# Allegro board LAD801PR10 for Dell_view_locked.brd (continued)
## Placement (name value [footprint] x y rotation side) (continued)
RC11  80.6_0402_1%  [R_0402]  92.58 39.82 180 top
RC12  100_0402_1%  [R_0402]  92.55 38.94 180 top
RC13  10K_0402_5%  [R_0402]  91.64 31.46 0 top
RC14  10K_0402_5%  [R_0402]  91.64 30.57 0 top
RC15  22_0402_5%  [R_0402]  96.11 25.19 270 bottom
RC16  22_0402_5%  [R_0402]  96.93 28.96 180 bottom
RC17  0_0603_5%  [R0603_0OHM]  88.47 21.74 180 top
RC18  4.7K_0402_5%  [R_0402]  105.94 22.12 90 bottom
RC19  1K_0402_5%  [R_0402]  106.85 20.54 180 bottom
RC20  1K_0402_5%  [R_0402]  92.96 15.54 0 bottom
RC21  33_0402_5%  [R_0402]  105.67 13.17 0 bottom
RC22  33_0402_5%  [R_0402]  103.78 25.18 270 bottom
RC23  33_0402_5%  [R_0402]  101.67 25.19 270 bottom
RC24  33_0402_5%  [R_0402]  99.89 25.19 270 bottom
RC25  33_0402_5%  [R_0402]  99 25.19 270 bottom
RC26  33_0402_5%  [R_0402]  102.76 25.18 270 bottom
RC27  2.2K_0402_5%  [R_0402]  113.48 25.86 0 top
RC28  2.2K_0402_5%  [R_0402]  114.65 21.68 180 top
RC29  1K_0402_5%  [R_0402]  114.57 22.83 270 bottom
RC30  1K_0402_5%  [R_0402]  115.46 22.83 270 bottom
RC31  1K_0402_5%  [R_0402]  115.53 25.12 270 bottom
RC32  1K_0402_5%  [R_0402]  116.41 25.12 270 bottom
RC33  1K_0402_5%  [R_0402]  118.01 25.18 270 bottom
RC34  1K_0402_5%  [R_0402]  113.75 25.12 270 bottom
RC35  8.2K_0402_5%  [R_0402]  98.22 33.7 225 bottom
RC36  8.2K_0402_5%  [R_0402]  97.06 31.13 180 bottom
RC37  8.2K_0402_5%  [R_0402]  113.68 22.83 270 bottom
RC38  10K_0402_5%  [R_0402]  114.64 25.12 270 bottom
RC39  150K_0402_5%  [R_0402]  110.57 21.73 90 bottom
RC40  1K_0402_1%  [R_0402]  100.78 24.28 90 bottom
RC41  1K_0402_1%  [R_0402]  106.85 19.65 180 bottom
RC42  10K_0402_5%  [R_0402]  111.91 21.91 90 bottom
RC43  49.9K_0402_1%  [R_0402]  111.7 26.37 0 top
RC44  4.7K_0402_5%  [R_0402]  97.35 24.3 90 bottom
RC45  10K_0402_5%  [R_0402]  88.23 22.82 180 top
RC46  10K_0402_5%  [R_0402]  119.81 25.19 270 bottom
RC47  10K_0402_5%  [R_0402]  109.94 25.06 270 bottom
RC48  10K_0402_5%  [R_0402]  118.9 25.18 270 bottom
RC49  10K_0402_5%  [R_0402]  116.99 21.86 90 bottom
RC50  150K_0402_5%  [R_0402]  117.87 21.86 90 bottom
RC51  10K_0402_5%  [R_0402]  96.41 27.93 0 bottom
RC52  10K_0402_5%  [R_0402]  97.33 27.04 180 bottom
RC53  10K_0402_5%  [R_0402]  85.62 27.25 90 top
RC54  10K_0402_5%  [R_0402]  86.51 28.17 270 top
RC55  10K_0402_5%  [R_0402]  112.79 21.92 90 bottom
RC56  10K_0402_5%  [R_0402]  112.86 25.12 270 bottom
RC57  10K_0402_5%  [R_0402]  85.55 25.56 270 top
RC58  10K_0402_5%  [R_0402]  86.44 24.65 90 top
RC59  10K_0402_5%  [R_0402]  84.73 27.25 90 top
RC60  10K_0402_5%  [R_0402]  90.46 30.69 180 top
RC61  10K_0402_5%  [R_0402]  87.46 27.21 270 top
RC62  10K_0402_5%  [R_0402]  88.35 26.3 90 top
RC63  10K_0402_5%  [R_0402]  117.11 20.39 0 bottom
RC64  10K_0402_5%  [R_0402]  120.85 24.28 90 bottom
RC65  100_0402_1%  [R_0402]  119.45 30.82 0 top
RC66  113_0402_1%  [R_0402]  112.26 32.14 90 top
RC67  1K_0402_5%  [R_0402]  109.05 25.06 270 bottom
RC68  1K_0402_5%  [R_0402]  108.16 25.06 270 bottom
RC69  10K_0402_5%  [R_0402]  121.89 25.19 270 bottom
RC70  10K_0402_5%  [R_0402]  120.31 27.83 270 top
RC71  10K_0402_5%  [R_0402]  87.38 24.85 0 top
RC72  10K_0402_5%  [R_0402]  96.44 26.15 0 bottom
RC73  10K_0402_5%  [R_0402]  87.38 23.96 0 top
RC74  0_0402_5%  [R_0402]  83.08 22.81 90 top
RC75  0_0402_5%  [R_0402]  82.12 21.22 90 top
RC76  2.71K_0402_1%  [R_0402]  125.74 50.88 0 bottom
RC77  20K_0402_5%  [R_0402]  91.65 21.5 270 top
RC78  20K_0402_5%  [R_0402]  89.86 20.6 0 top
RC80  1M_0402_1%  [R_0402]  129.33 47.78 90 bottom
RC82  10M_0402_5%  [R_0402]  91.38 28.22 0 top
RC83  0_0402_5%  [R0402_0OHM]  89.6 28.22 0 top
RC84  10K_0402_5%  [R_0402]  92.55 22.63 180 top
RC85  10K_0402_5%  [R_0402]  93.52 13.1 0 bottom
RC86  10K_0402_5%  [R_0402]  122.78 24.28 90 bottom
RC87  100K_0402_5%  [R_0402]  97.19 38.5 180 bottom
RC88  10K_0402_5%  [R_0402]  36.4 3.12 90 top
RC89  8.2K_0402_5%  [R_0402]  89.03 33.04 0 top
RC90  10K_0402_5%  [R_0402]  92.36 34.19 180 top
RC91  330K_0402_5%  [R_0402]  85.93 23.33 180 top
RC92  10K_0402_5%  [R_0402]  108.03 18.9 270 bottom
RC93  100K_0402_5%  [R_0402]  89.95 34 180 top
RC94  10K_0402_5%  [R_0402]  83.11 24.97 90 top
RC95  1K_0402_5%  [R_0402]  125.82 73.24 180 bottom
RC96  60.4_0402_1%  [R_0402]  127.67 68.29 180 bottom
RC97  0_0402_5%  [R0402_0OHM]  98.63 38.49 90 bottom
RC99  0_0402_5%  [R0402_0OHM]  83.97 20.2 90 top
RC100  0_0402_5%  [R_0402]  95.3 12.21 90 bottom
RC102  1M_0402_5%  [R_0402]  84.92 14.77 270 top
RC103  10K_0402_1%  [R_0402]  88.86 10.93 90 top
RC104  1K_0402_5%  [R_0402]  130.63 54.45 180 bottom
RC105  10K_0402_5%  [R_0402]  125.85 24.28 0 bottom
RC106  0_0402_5%  [R0402_0OHM]  128.52 24.28 180 bottom
RC107  0_0402_5%  [R0402_0OHM]  126.77 25.16 180 bottom
RC108  0_0402_5%  [R_0402]  105.95 14.1 90 bottom
RC109  100K_0402_5%  [R_0402]  105.95 15.87 90 bottom
RC110  1K_0402_5%  [R_0402]  83.97 23.72 270 top
RC111  49.9_0402_1%  [R_0402]  127.48 63.05 180 bottom
RC112  1K_0402_5%  [R_0402]  128.34 63.02 0 bottom
RC113  1K_0402_5%  [R_0402]  129.45 67.71 180 bottom
RC114  10K_0402_5%  [R_0402]  93.17 17.29 180 bottom
RC115  10K_0402_5%  [R_0402]  130.26 28.78 90 bottom
RC116  10K_0402_5%  [R_0402]  129.32 29.81 180 bottom
RC117  499_0402_1%  [R_0402]  127.6 67.33 180 bottom
RC118  0_0402_5%  [R_0402]  129.32 30.69 180 bottom
RC119  49.9_0402_1%  [R_0402]  92.55 36.28 180 top
RC120  49.9_0402_1%  [R_0402]  92.55 37.17 180 top
RC121  49.9_0402_1%  [R_0402]  126.75 70.06 0 bottom
RC122  49.9_0402_1%  [R_0402]  126.75 69.18 0 bottom
RC123  33_0402_5%  [R_0402]  78.52 21.12 90 top
RC124  33_0402_5%  [R_0402]  80.79 18.05 90 top
RC125  33_0402_5%  [R_0402]  79.9 18.05 90 top
RC126  1K_0402_5%  [R_0402]  79.01 18.05 90 top
RC127  33_0402_5%  [R_0402]  79.42 21.11 90 top
RC128  8.2K_0402_5%  [R_0402]  108.96 18.64 90 bottom
RC129  4.7K_0402_5%  [R_0402]  109.85 18.64 90 bottom
RC130  200_0402_1%  [R_0402]  110.89 25.06 270 bottom
RC131  10K_0402_1%  [R_0402]  128.56 73.19 270 bottom
RC132  10K_0402_1%  [R_0402]  127.64 73.2 180 bottom
RC133  10K_0402_1%  [R_0402]  123.84 73.25 270 bottom
RC134  49.9_0402_1%  [R_0402]  128.34 62.06 0 bottom
RC136  10K_0402_1%  [R_0402]  120.35 69.92 90 top
RC137  0_0402_5%  [R_0402]  113.3 29.22 90 top
RC138  100K_0402_5%  [R_0402]  128.48 66.84 270 bottom
RC139  1K_0402_5%  [R_0402]  92.96 14.65 0 bottom
RC140  51_0402_5%  [R_0402]  128.34 61.11 0 bottom
RC141  51_0402_5%  [R_0402]  119.08 61.99 90 top
RC142  51_0402_5%  [R_0402]  128.15 58.82 0 bottom
RC143  1K_0402_5%  [R_0402]  131.77 22.45 180 bottom
RC144  0_0402_5%  [R_0402]  130.33 73.23 180 bottom
RC145  0_0402_5%  [R_0402]  105.91 18.1 0 bottom
RC146  51_0402_1%  [R_0402]  126.56 62.16 0 bottom
RC147  51_0402_5%  [R_0402]  129.04 59.71 0 bottom
RC148  1K_0402_5%  [R_0402]  82.19 25.88 270 top
RC149  0_0603_5%  [R_0603]  132.81 23.63 270 bottom
RC150  100_0402_1%  [R_0402]  132.04 52.14 90 top
RC151  100_0402_1%  [R_0402]  132.04 53.92 90 top
RC152  56_0402_1%  [R_0402]  129.38 64.79 180 bottom
RC153  220_0402_5%  [R_0402]  126.69 64.79 0 bottom
RC154  100_0402_1%  [R_0402]  127.6 66.38 180 bottom
RC155  100_0402_1%  [R_0402]  117.37 72.36 270 bottom
RC156  100_0402_1%  [R_0402]  116.41 71.45 90 bottom
RC157  100_0402_1%  [R_0402]  107.71 61.67 90 top
RC158  100_0402_1%  [R_0402]  106.89 63.45 90 top
RC159  100_0402_1%  [R_0402]  117.52 41.57 315 top
RC160  100_0402_1%  [R_0402]  119 41.53 90 top
RC161  0_0603_5%  [R0603_0OHM]  130.44 45.1 0 bottom
RC162  0_0603_5%  [R0603_0OHM]  131.4 43.83 0 bottom
RC163  0_0603_5%  [R0603_0OHM]  92.74 15.25 180 top
RC164  10K_0402_5%  [R_0402]  85.93 15.71 90 top
RC169  0_0603_5%  [R0603_0OHM]  131.45 28.13 270 bottom
RC170  0_0603_5%  [R0603_0OHM]  135.38 41.6 180 top
RC171  0_0603_5%  [R0603_0OHM]  135.26 44.08 270 top
RC173  0_0603_5%  [R0603_0OHM]  135.47 45.23 270 bottom
RC174  0_0603_5%  [R0603_0OHM]  130.3 23.52 0 bottom
RC175  0_0402_5%  [R_0402]  130.77 75.09 270 bottom
RC176  15_0402_1%  [R_0402]  116.27 18.06 0 bottom
RC177  15_0402_1%  [R_0402]  113.51 17.8 180 bottom
RC178  15_0402_1%  [R_0402]  108.68 12.1 180 bottom
RC179  15_0402_1%  [R_0402]  108.68 11.21 180 bottom
RC180  15_0402_1%  [R_0402]  119.44 12.57 0 bottom
RC181  10K_0402_5%  [R_0402]  117.11 19.5 0 bottom
RC182  10K_0402_5%  [R_0402]  115.74 19.45 180 bottom
RC187  10K_0402_5%  [R_0402]  97.77 32 45 bottom
RC188  10K_0402_5%  [R_0402]  76.52 17.04 0 top
RC189  0_0402_5%  [R_0402]  81.24 21.09 90 top
RC190  10K_0402_5%  [R_0402]  85.88 20.31 0 top
RC191  10K_0402_5%  [R_0402]  86.81 19.41 180 top
RC192  1M_0402_1%  [R_0402]  87.99 10.95 180 top
RD1  0_0402_5%  [R_0402]  60.28 18.93 90 top
RD2  0_0402_5%  [R_0402]  66.39 19.77 180 top
RD3  0_0402_5%  [R_0402]  58.57 41.16 90 top
RD4  0_0402_5%  [R0402_0OHM]  61.17 19.85 270 top
RD5  0_0402_5%  [R0402_0OHM]  64.6 19.79 270 top
RD6  0_0402_5%  [R0402_0OHM]  59.45 42.07 270 top
RD7  470_0402_1%  [R_0402]  58.44 63.54 0 top
RD8  0_0402_5%  [R0402_0OHM]  60.21 62.63 90 top
RD9  2_0402_1%  [R_0402]  57.73 43.39 0 top
RD10  1K_0402_1%~D  [R_0402]  58.63 46.07 270 top
RD11  24.9_0402_1%  [R_0402]  55.95 44.28 0 top
RD12  1K_0402_1%~D  [R_0402]  58.64 44.28 180 top
RD13  0_0402_5%  [R_0402]  50.95 20.61 270 top
RD14  0_0402_5%  [R0402_0OHM]  45.73 20.66 0 top
RD15  0_0402_5%  [R_0402]  44.46 43.33 0 top
RD16  0_0402_5%  [R0402_0OHM]  50.06 20.61 270 top
RD17  0_0402_5%  [R_0402]  47.47 21.68 180 top
RD18  0_0402_5%  [R0402_0OHM]  45.37 42.44 180 top
RD19  2_0402_1%  [R_0402]  44.46 46.06 0 top
RD20  1K_0402_1%~D  [R_0402]  44.46 46.95 0 top
RD21  1K_0402_1%~D  [R_0402]  45.37 45.17 180 top
RD22  24.9_0402_1%  [R_0402]  42.68 45.17 0 top
RD23  240_0402_1%  [R_0402]  58.68 53.87 0 top
RD24  240_0402_1%  [R_0402]  44.85 53.73 90 top
RE1  100K_0402_1%  [R_0402]  148.34 13.31 0 bottom
RE2  0_0603_5%  [R0603_0OHM]  141.18 19.26 180 top
RE3  100K_0402_1%  [R_0402]  151.03 21.41 180 top
RE4  100K_0402_1%  [R_0402]  151.03 20.52 180 top
RE6  100K_0402_1%  [R_0402]  147.83 14.18 0 bottom
RE7  0_0603_5%  [R0603_0OHM]  146.26 13.99 270 bottom
RE8  4.7K_0402_5%  [R_0402]  138.46 20.6 180 bottom
RE9  4.7K_0402_5%  [R_0402]  138.46 21.49 180 bottom
RE10  2.2K_0402_5%  [R_0402]  138.46 22.5 180 bottom
RE11  2.2K_0402_5%  [R_0402]  138.46 23.39 180 bottom
RE12  10K_0402_5%  [R_0402]  139.73 34.57 180 bottom
RE13  10K_0402_5%  [R_0402]  144.91 32.85 0 top
RE14  100K_0402_5%  [R_0402]  141.51 34.57 180 bottom
RE15  100K_0402_5%  [R_0402]  155.26 29.87 0 top
RE16  10K_0402_5%  [R_0402]  153.56 28.26 90 top
RE17  100K_0402_5%  [R_0402]  138.4 24.85 180 bottom
RE18  100K_0402_5%  [R_0402]  138.46 18.69 180 bottom
RE19  1K_0402_5%  [R_0402]  153.64 25.04 180 top
RE20  10K_0402_5%  [R_0402]  157.87 22.12 0 bottom
RE21  100K_0402_5%  [R_0402]  154.32 14.9 270 top
RE22  0_0402_5%  [R0402_0OHM]  155.58 20.47 0 top
RE23  43_0402_1%  [R_0402]  158.13 18.39 270 top
RE24  0_0402_5%  [R_0402]  147.83 14.18 0 top
RE25  100K_0402_5%  [R_0402]  144.98 35.96 0 top
RE26  0_0402_5%  [R_0402]  154.66 16.27 180 top
RE27  0_0402_5%  [R_0402]  153.26 33.36 180 top
RE28  0_0402_5%  [R0402_0OHM]  146.27 15.22 180 top
RE29  1K_0402_5%  [R_0402]  146.27 19.58 90 top
RE30  100K_0402_5%  [R_0402]  142.63 17.49 0 top
RE32  100K_0402_5%  [R_0402]  145.38 19.58 90 top
RE33  15_0402_1%  [R_0402]  138.07 30.8 90 bottom
RE34  15_0402_1%  [R_0402]  137.55 28.26 0 bottom
RE35  15_0402_1%  [R_0402]  137.55 29.14 0 bottom
RE37  0_0402_5%  [R0402_0OHM]  137.94 27.21 270 bottom
RE38  0_0402_5%  [R0402_0OHM]  136.94 26.82 180 bottom
RE40  10K_0402_5%  [R_0402]  145.62 17.69 270 top
RE41  100K_0402_5%  [R_0402]  139.46 14.11 90 bottom
RE42  0_0402_5%  [R0402_0OHM]  147.94 34.61 180 bottom
RE43  100_0402_5%  [R_0402]  140.35 15.02 270 bottom
RE44  0_0402_5%  [R_0402]  148.75 15.07 180 top
RE45  0_0402_5%  [R_0402]  142.93 13.54 180 bottom
RE46  10K_0402_1%  [R_0402]  143.22 28.54 180 top
RE47  0_0402_5%  [R_0402]  143.77 14.57 0 bottom
RE48  10K_0402_1%  [R_0402]  140.93 28.79 270 top
RE49  100K_0402_5%  [R_0402]  144.3 26.69 180 top
RE50  0_0603_5%  [R0603_0OHM]  148.58 17 0 top
RE51  300_0402_5%  [R_0402]  149.22 19.57 90 top
RE52  100K_0402_5%  [R_0402]  143.01 25.8 0 top
RE53  100K_0402_5%  [R_0402]  152.84 23.95 0 top
RE54  300_0402_5%  [R_0402]  147.43 19.57 90 top
RE55  10K_0402_5%  [R_0402]  132.73 11.09 270 top
RE56  10K_0402_5%  [R_0402]  136.29 12.41 270 top
RE57  100K_0402_5%  [R_0402]  133.62 11.09 270 top
RE58  49.9_0402_1%  [R_0402]  128.29 11.09 270 top
RE59  10K_0402_5%  [R_0402]  133.61 12.78 0 top
RE60  0_0402_5%  [R0402_0OHM]  134.53 14.69 180 top
RE61  0_0402_5%  [R0402_0OHM]  136.3 14.05 180 top
RE63  0_0402_5%  [R0402_0OHM]  134.53 13.67 180 top
RE64  0_0402_5%  [R0402_0OHM]  149.44 15.96 180 top
RI1  5.6_0402_1%  [R_0402]  17.29 86.32 180 top
RI2  5.6_0402_1%  [R_0402]  17.29 87.21 180 top
RI3  150_0402_5%  [R_0402]  14.93 87.22 270 top
RI4  5.6_0402_1%  [R_0402]  17.29 89.75 180 top
RI5  5.6_0402_1%  [R_0402]  17.29 88.86 180 top
RI6  150_0402_5%  [R_0402]  14.93 89.83 270 top
RI7  5.6_0402_1%  [R_0402]  17.29 81.24 180 top
RI8  5.6_0402_1%  [R_0402]  17.29 82.13 180 top
RI9  150_0402_5%  [R_0402]  14.93 82.14 270 top
RI10  5.6_0402_1%  [R_0402]  17.29 83.78 180 top
RI11  5.6_0402_1%  [R_0402]  17.29 84.67 180 top
RI12  150_0402_5%  [R_0402]  14.93 84.68 270 top
RI13  2.2K_0402_5%  [R_0402]  26.7 95.46 180 top
RI14  2.2K_0402_5%  [R_0402]  26.7 96.48 180 top
RI15  1M_0402_5%  [R_0402]  24.85 93.06 270 top
RI16  20K_0402_5%  [R_0402]  29.29 92.17 270 top
RL1  10K_0402_5%  [R_0402]  35.38 123.15 0 bottom
RL2  2.49K_0402_1%~D  [R_0402]  39.27 115.72 180 bottom
RL3  1K_0402_5%  [R_0402]  34.94 121.7 270 bottom
RL4  15K_0402_1%  [R_0402]  35.96 120.79 90 bottom
RL5  0_0603_5%  [R0603_0OHM]  38.56 115.4 90 top
RL6  100K_0402_5%  [R_0402]  25.55 122.57 90 bottom
RL7  10K_0402_5%  [R_0402]  25.55 121.7 270 bottom
RL12  0_0402_5%  [R0402_0OHM]  41.12 109.12 180 top
RL13  0_0402_5%  [R0402_0OHM]  27.2 118.69 90 top
RL14  75_0603_5%  [R_0603]  19.89 112.1 180 top
RL15  75_0603_5%  [R_0603]  19.89 108.29 180 top
RL16  10K_0402_5%  [R_0402]  31.2 115.13 90 bottom
RP1  100K_8P4R_5%  [RP_0804_8P4R]  222.9 38.87 0 top
RP2  100_8P4R_5%  [RP_0804_8P4R]  224.11 43.53 180 top
RP34  10K_8P4R_5%  [RP_0804_8P4R]  117.48 95.97 90 bottom
RPC1  10K_8P4R_5%  [RP_0804_8P4R]  130.76 30.96 0 bottom
RPE1  10K_8P4R_5%  [RP_0804_8P4R]  142.92 21.68 0 top
RPE2  10K_8P4R_5%  [RP_0804_8P4R]  152.34 14.06 270 top
RPE3  100K_8P4R_5%  [RP_0804_8P4R]  144.1 23.2 180 top
RPE4  100K_8P4R_5%  [RP_0804_8P4R]  143.35 36.16 270 bottom
RPE5  100K_8P4R_5%  [RP_0804_8P4R]  159.85 29.22 180 bottom
RPE6  100K_8P4R_5%  [RP_0804_8P4R]  159.92 20.84 180 bottom
RPI1  470_8P4R_5%  [RP_0804_8P4R]  15.08 82.29 0 bottom
RPI2  470_8P4R_5%  [RP_0804_8P4R]  15.07 87.11 0 bottom
RS1  0_0402_5%  [R_0402]  195.97 17.28 180 top
RU1  0_0402_5%  [R_0402-NPM]  25.34 57.87 0 top
RU2  0_0402_5%  [R_0402-NPM]  25.34 56.98 0 top
RU3  0_0402_5%  [R_0402]  22.61 61.62 0 top
RU4  0_0402_5%  [R_0402]  22.61 62.51 0 top
RU5  0_0402_5%  [R_0402]  22.61 59.84 0 top
RU6  0_0402_5%  [R_0402]  22.61 60.73 0 top
RU7  0_0402_5%  [R_0402-NPM]  26.76 35.2 180 top
RU8  0_0402_5%  [R_0402-NPM]  26.76 36.09 180 top
RU9  0_0402_5%  [R_0402]  22.8 40.54 0 top
RU10  0_0402_5%  [R_0402]  22.8 41.43 0 top
RU11  0_0402_5%  [R_0402]  22.93 38.19 0 top
RU12  0_0402_5%  [R_0402]  22.93 39.08 0 top
RU13  0_0402_5%  [R_0402-NPM]  173.71 20.43 0 bottom
RU14  0_0402_5%  [R_0402-NPM]  173.71 19.55 0 bottom
RU15  0_0402_5%  [R_0402-NPM]  179.72 20.42 0 bottom
RU16  0_0402_5%  [R_0402-NPM]  179.72 19.53 0 bottom
RV1  1.69K_0402_1%  [R_0402]  110.37 120.04 90 top
RV2  1K_0402_1%  [R_0402]  113.69 109.36 0 top
RV3  1K_0402_1%  [R_0402]  109.29 120.04 90 top
RV4  100K_0402_5%  [R_0402]  98.81 122.38 270 bottom
RV5  45.3K_0402_1%  [R_0402]  111.78 100.6 90 top
RV6  45.3K_0402_1%  [R_0402]  113.16 104.6 0 top
RV8  8.45K_0402_1%  [R_0402]  104.8 115.19 90 top
RV9  2K_0402_1%  [R_0402]  105.7 116.09 270 top
RV11  8.45K_0402_1%  [R_0402]  103 117.53 270 top
RV12  2K_0402_1%  [R_0402]  103.9 116.63 90 top
RV13  4.75K_0402_1%  [R_0402]  103 114.83 90 top
RV15  8.45K_0402_1%  [R_0402]  102.2 120.49 0 top
RV16  4.75K_0402_1%  [R_0402]  103.45 119.59 180 top
RV17  1K_0402_1%  [R_0402]  117.76 101.35 90 top
RV20  1M_0402_5%  [R_0402]  98.82 124.94 270 bottom
RV21  10K_0402_5%  [R_0402]  113.05 98.62 90 bottom
RV27  0_0603_5%  [R0603_0OHM]  102.16 110.25 180 top
RV28  8.45K_0402_1%  [R_0402]  101.93 115.73 270 top
RV29  10K_0402_5%  [R_0402]  107.24 120.71 270 top
RV30  0_0603_5%  [R0603_0OHM]  103.05 109 180 top
RV31  0_0603_5%  [R0603_0OHM]  109.3 124.16 0 top
RV32  40.2_0402_1%  [R_0402]  120.48 127.33 90 bottom
RV33  40.2_0402_1%  [R_0402]  119.6 127.34 180 bottom
RV34  100_0402_1%  [R_0402]  117.82 128.23 180 bottom
RV35  100_0402_1%  [R_0402]  120.55 129.12 180 bottom
RV36  49.9_0402_1%  [R_0402]  134.39 96.43 270 bottom
RV37  10_0402_1%  [R_0402]  133.49 96.43 270 bottom
RV38  5.1K_0402_1%  [R_0402]  132.6 96.43 270 bottom
RV39  120_0402_1%  [R_0402]  110.81 126.32 0 top
RV40  51.1_0402_1%  [R_0402]  118.83 100.02 90 top
RV41  51.1_0402_1%  [R_0402]  117.73 100.11 180 top
RV48  2.37K_0402_1%  [R_0402]  154.27 101.88 180 top
RV49  5.49K_0402_1%  [R_0402]  153.36 103.66 0 top
RV50  2.37K_0402_1%  [R_0402]  144.61 96.66 90 bottom
RV51  5.49K_0402_1%  [R_0402]  142.83 97.57 270 bottom
RV52  2.37K_0402_1%  [R_0402]  153.18 127.16 270 top
RV53  5.49K_0402_1%  [R_0402]  153.1 124.42 0 top
RV54  2.37K_0402_1%  [R_0402]  143.76 130.9 270 bottom
RV55  5.49K_0402_1%  [R_0402]  142.74 129.98 90 bottom
RV59  10K_0402_5%  [R_0402]  108.3 120.95 270 top
RV79  120_0402_1%  [R_0402]  143.76 130.88 270 top
RV80  120_0402_1%  [R_0402]  144.65 130.88 270 top
RV81  4.7K_0402_5%  [R_0402]  110.19 100.29 270 bottom
RV82  4.7K_0402_5%  [R_0402]  111.09 100.29 270 bottom
RV83  16.2K_0402_1%  [R_0402]  109.29 100.29 270 bottom
RV84  10K_0402_5%  [R_0402]  98.08 108.03 180 bottom
RV85  120_0402_1%  [R_0402]  144.61 96.66 90 top
RV86  120_0402_1%  [R_0402]  143.72 96.66 90 top
RV87  10K_0402_5%  [R_0402]  98.06 108.93 180 bottom
RV88  10K_0402_5%  [R_0402]  97.14 109.83 0 bottom
RV89  10K_0402_5%  [R_0402]  99.85 108.03 180 bottom
RV116  1K_0402_1%  [R_0402]  144.21 113.37 0 top
RV117  1K_0402_1%  [R_0402]  144.21 113.37 0 bottom
RV118  1K_0402_1%  [R_0402]  153.36 104.54 0 top
RV119  1K_0402_1%  [R_0402]  153.36 104.54 0 bottom
RV120  121_0402_1%  [R_0402]  142.83 97.57 270 top
RV121  121_0402_1%  [R_0402]  141.94 97.57 270 bottom
RV123  121_0402_1%  [R_0402]  145.55 130 90 top
RV131  1K_0402_1%  [R_0402]  144.21 114.32 0 bottom
RV132  121_0402_1%  [R_0402]  145.55 130 90 bottom
RV133  1K_0402_1%  [R_0402]  153.1 123.47 0 bottom
RV134  1K_0402_1%  [R_0402]  144.21 114.32 0 top
RV135  1K_0402_1%  [R_0402]  153.1 123.47 0 top
RV151  10K_0402_5%  [R_0402]  116.39 99.48 90 bottom
RV152  10K_0402_5%  [R_0402]  114.95 100.37 270 bottom
RV153  0_0402_5%  [R_0402]  114 99.39 90 bottom
RV154  5.1K_0402_1%  [R_0402]  116.86 101.35 90 top
RV155  0_0402_5%  [R0402_0OHM]  99.85 111.02 180 bottom
RV156  0_0402_5%  [R0402_0OHM]  99.85 110.15 180 bottom
RV157  0_0402_5%  [R0402_0OHM]  99.85 109.25 180 bottom
RV158  0_0402_5%  [R0402_0OHM]  105.43 119.05 90 top
RV159  0_0402_5%  [R0402_0OHM]  106.33 119.05 90 top
RV162  4.7K_0402_5%  [R_0402]  97.97 119.41 0 bottom
RV163  4.7K_0402_5%  [R_0402]  98.88 120.31 180 bottom
RV260  4.7K_0402_5%  [R_0402]  119.59 97 270 bottom
RV364  0_0603_5%  [R0603_0OHM]  106.71 98.1 180 bottom
RV368  10K_0402_5%  [R_0402]  114.05 101.24 0 bottom
RV369  10K_0402_5%  [R_0402]  115.15 100.08 90 top
RW1  0_0402_5%  [R_0402]  42.82 97.29 270 bottom
RW2  0_0402_5%  [R_0402]  41.93 97.29 270 bottom
RW3  0_0805_5%  [R_0805]  60.28 106.77 270 top
RW4  0_0402_5%  [R0402_0OHM]  55.84 109.64 270 top
RW5  0_0805_5%  [R_0805]  56.99 105.91 0 top
RW6  0_0402_5%  [R_0402]  53.93 104.72 90 top
RW8  100K_0402_5%  [R_0402]  52.14 105.69 0 top
RW9  0_0402_5%  [R0402_0OHM]  59.42 98.29 180 bottom
RX1  10K_0402_5%  [R_0402]  222.21 53.44 270 top
RX2  10K_0402_5%  [R_0402]  221.32 53.44 270 top
RX3  100K_0402_5%  [R_0402]  220.43 52.53 90 top
RX4  0_0402_5%  [R_0402-NPM]  219.08 42.92 90 bottom
RX5  4.99K_0402_1%  [R_0402]  208.44 38.06 180 bottom
RX6  0_0402_5%  [R_0402]  216.49 38.45 270 bottom
RX7  0_0402_5%  [R_0402-NPM]  218.19 42.92 90 bottom
RX8  0_0402_5%  [R_0402-NPM]  216.39 42.95 90 bottom
RX9  0_0402_5%  [R_0402-NPM]  217.28 42.95 90 bottom
RX10  10K_0402_5%  [R_0402]  218.45 45.93 90 top
RX11  3.3K_0402_5%  [R_0402]  210.27 36.65 90 bottom
RX12  0_0402_5%  [R_0402]  210.27 39.72 270 top
RX13  10K_0402_5%  [R_0402]  217.53 45.93 90 top
RX14  3.3K_0402_5%  [R_0402]  215.35 45.88 270 bottom
RX15  0_0402_5%  [R_0402]  215.35 45.88 270 top
RX16  4.7K_0402_5%  [R_0402]  211.79 45.88 270 bottom
RX17  4.7K_0402_5%  [R_0402]  211.79 45.88 270 top
RX18  4.7K_0402_5%  [R_0402]  211.16 36.65 90 bottom
RX19  4.7K_0402_5%  [R_0402]  211.16 39.72 270 top
RX20  4.7K_0402_5%  [R_0402]  212.68 45.88 270 bottom
RX21  4.7K_0402_5%  [R_0402]  212.68 45.88 270 top
RX22  4.7K_0402_5%  [R_0402]  213.57 45.88 270 bottom
RX23  4.7K_0402_5%  [R_0402]  213.57 45.88 270 top
RX24  4.7K_0402_5%  [R_0402]  214.46 45.88 270 bottom
RX25  4.7K_0402_5%  [R_0402]  214.46 45.88 270 top
RX26  4.7K_0402_5%  [R_0402]  212.05 36.65 90 bottom
RX27  4.7K_0402_5%  [R_0402]  212.49 39.74 270 top
RX28  4.7K_0402_5%  [R_0402]  212.93 36.65 90 bottom
RX29  4.7K_0402_5%  [R_0402]  214.27 39.06 180 top
RX30  4.7K_0402_5%  [R_0402]  213.82 36.65 90 bottom
RX31  4.7K_0402_5%  [R_0402]  215.31 38.17 180 top
RZ1  22.1K_0402_1%  [R_0402]  136.39 32.68 270 top
RZ2  0_0402_5%  [R_0402]  136.99 26.3 90 top
RZ3  49.9K_0402_1%  [R_0402]  139.02 28.07 90 top
RZ4  0_0603_5%  [R_0603]  135.13 39.86 270 top
RZ6  0_0402_5%  [R_0402]  129.29 91.74 180 bottom
RZ7  10K_0402_5%  [R_0402]  118.84 92.48 180 bottom
RZ8  10K_0402_5%  [R_0402]  118.84 90.68 180 bottom
RZ9  1M_0402_1%  [R_0402]  137.24 32.66 0 top
SW1  TST71-N-220-T170-S017_2P  [SW_TST71-N-220-T170-S017_2P]  157.18 100.13 270 top
TL1  NS14-1 LF 10/100 BASE-TX  [MHPC_NS681677_12P]  28.02 114.64 270 bottom
TP1  PAD  [TPC12]  119.25 54.73 0 top
TP2  PAD  [TPC12]  120.5 55.03 0 top
TP3  PAD  [TPC12]  96.18 62.11 180 bottom
TP4  PAD  [TPC12]  97.05 63.09 180 bottom
TP5  PAD  [TPC12]  106.57 59.58 0 top
TP6  PAD  [TPC12]  105.87 58.25 0 top
TP7  PAD  [TPC12]  126.33 74.25 180 bottom
TP8  PAD  [TPC12]  119.69 52.05 0 top
TP9  PAD  [TPC12]  121.9 52.8 0 top
TP10  PAD  [TPC12]  103.84 36.85 0 top
TP11  PAD  [TPC12]  96.07 37.29 180 bottom
TP12  PAD  [TPC12]  104.92 36.15 0 top
TP13  PAD  [TPC12]  107.21 33.93 0 top
TP14  PAD  [TPC12]  130.17 63.05 180 bottom
TP15  PAD  [TPC12]  127.22 58.86 180 bottom
TP16  PAD  [TPC12]  124.85 59.21 180 bottom
TP17  PAD  [TPC12]  125.95 58.55 180 bottom
TP18  PAD  [TPC12]  125.93 59.92 180 bottom
TP19  PAD  [TPC12]  99.21 73.3 180 bottom
TP20  PAD  [TPC12]  97.55 73.3 180 bottom
TP21  PAD  [TPC12]  96.45 71.89 180 bottom
TP22  PAD  [TPC12]  97.86 71.96 180 bottom
TP23  PAD  [TPC12]  108.54 36.4 0 top
TP24  PAD  [TPC12]  108.16 35.14 0 top
TP25  PAD  [TPC12]  103.83 31.09 0 top
TP26  PAD  [TPC12]  106 30.19 0 top
TP27  PAD  [TPC12]  96.74 23.22 180 bottom
TP28  PAD  [TPC12]  95.93 20.92 180 bottom
TP29  PAD  [TPC12]  96.88 21.87 180 bottom
TP30  PAD  [TPC12]  100.91 73.11 180 bottom
TP31  PAD  [TPC12]  99.98 72.19 180 bottom
TP32  PAD  [TPC12]  118.51 46.76 0 top
TP33  PAD  [TPC12]  108.16 46.76 0 top
TP34  PAD  [TPC12]  112.4 64.29 0 top
TP35  PAD  [TPC12]  111.4 63.46 0 top
TP36  PAD  [TPC12]  108.08 63.78 0 top
TP37  PAD  [TPC12]  109.13 62.01 0 top
TP38  PAD  [TPC12]  107.27 42.19 0 top
TP39  PAD  [TPC12]  107.97 40.54 0 top
TP40  PAD  [TPC12]  62.31 45.24 0 top
TP41  PAD  [TPC12]  66 43.65 0 top
TP42  PAD  [TPC12]  52.03 43.9 0 top
TP43  PAD  [TPC12]  46.69 45.8 0 top
TP44  PAD  [TPC12]  138.51 25.61 90 bottom
TP46  PAD  [TPC12]  200.3 46.06 180 bottom
TP47  PAD  [TPC12]  192.96 45.32 180 bottom
TP48  PAD  [TPC12]  38.16 117.24 180 bottom
TP49  PAD  [TPC12]  36.72 119.92 180 bottom
TP50  PAD  [TPC12]  114.62 108.35 0 top
TP51  PAD  [TPC12]  115.92 108.21 0 top
TP52  PAD  [TPC12]  106.22 108.06 0 top
TP53  PAD  [TPC12]  111.94 108.91 0 top
TP54  PAD  [TPC12]  106.03 106.8 0 top
TP55  PAD  [TPC12]  105.91 109.31 0 top
TP56  PAD  [TPC12]  108.91 108.79 0 top
TP57  PAD  [TPC12]  107.25 105.61 0 top
TP58  PAD  [TPC12]  107.64 108.34 0 top
TP59  PAD  [TPC12]  108.01 104.58 0 top
TP60  PAD  [TPC12]  108.76 107.5 0 top
TP61  PAD  [TPC12]  107.63 106.86 0 top
TP62  PAD  [TPC12]  108.61 106.01 0 top
TP63  PAD  [TPC12]  106 101.3 180 bottom
TP64  PAD  [TPC12]  107.46 101.24 180 bottom
TP65  PAD  [TPC12]  111.22 106.04 0 top
TP66  PAD  [TPC12]  109.91 106.1 0 top
TP67  PAD  [TPC12]  109.93 102.14 180 bottom
TP68  PAD  [TPC12]  108.85 101.33 180 bottom
TP69  PAD  [TPC12]  113.52 102.15 180 bottom
TP70  PAD  [TPC12]  112.07 101.71 180 bottom
TP71  PAD  [TPC12]  158.14 18.12 180 bottom
TP72  PAD  [TPC12]  99.97 106.98 180 bottom
TP73  PAD  [TPC12]  108.03 113.76 0 top
TP74  PAD  [TPC12]  79.71 20.02 0 top
TP75  PAD  [TPC12]  106.83 36.53 0 top
TPC1  PAD  [TPC12]  128.14 59.76 270 bottom
TPC2  PAD  [TPC12]  125.61 62.46 180 bottom
TPC3  PAD  [TPC12]  127.24 60.66 180 bottom
TPC4  PAD  [TPC12]  126.11 61.27 180 bottom
TPC5  PAD  [TPC12]  120.11 62.3 0 top
TPC6  PAD  [TPC12]  125.19 63.68 180 bottom
TPC7  PAD  [TPC12]  126.46 26.41 180 bottom
TPC8  PAD  [TPC12]  94.98 15.51 180 bottom
TPC9  PAD  [TPC12]  104.88 15.39 180 bottom
TPC10  PAD  [TPC12]  129.53 72.27 180 bottom
TPC11  PAD  [TPC12]  127.02 71.86 180 bottom
TPC12  PAD  [TPC12]  129.06 70.74 180 bottom
TPC13  PAD  [TPC12]  129.84 74.95 180 bottom
TPC14  PAD  [TPC12]  120.39 71.8 0 top
TPC15  PAD  [TPC12]  122.91 72.09 180 bottom
TPC16  PAD  [TPC12]  121.61 72.05 180 bottom
TPC17  PAD  [TPC12]  122.78 74.41 180 bottom
TPC18  PAD  [TPC12]  119.91 65.24 0 top
TPC19  PAD  [TPC12]  120.7 66.31 0 top
TPC20  PAD  [TPC12]  121.01 73.45 180 bottom
TPC21  PAD  [TPC12]  118.9 72.17 180 bottom
TPC22  PAD  [TPC12]  122.26 73.2 180 bottom
TPC23  PAD  [TPC12]  119.78 73.94 180 bottom
TPC24  PAD  [TPC12]  118.51 74.74 180 bottom
TPC25  PAD  [TPC12]  119.67 71.09 180 bottom
TPC26  PAD  [TPC12]  118.59 73.46 180 bottom
TPC27  PAD  [TPC12]  120.16 72.43 180 bottom
TPC28  PAD  [TPC12]  120.21 67.56 0 top
TPC29  PAD  [TPC12]  116.86 74.38 180 bottom
TPC30  PAD  [TPC12]  120.48 63.52 0 top
TPC31  PAD  [TPC12]  124.84 61.37 180 bottom
TPC32  PAD  [TPC12]  82.11 23.98 0 top
TPC33  PAD  [TPC12]  131.24 73.23 180 bottom
TPS1  PAD  [TPC12]  123.44 25.37 180 bottom
TPS2  PAD  [TPC12]  104.79 34.89 0 top
TPS3  PAD  [TPC12]  135.46 24.53 180 bottom
TPS4  PAD  [TPC12]  96.02 35.55 180 bottom
TPS5  PAD  [TPC12]  97.06 36.33 180 bottom
TPS6  PAD  [TPC12]  105.43 38.5 0 top
TPS7  PAD  [TPC12]  91 18.46 0 top
TPS9  PAD  [TPC12]  165.99 25.25 180 top
TPS10  PAD  [TPC12]  161.01 23.74 180 top
U1  -  [SY6288C20AAC_SOT23-5]  224.59 24.23 90 bottom
U2  -  [NCT7718W_MSOP8]  132.59 14.73 90 bottom
UA1  ALC3246-CG_MQFN48_6X6  [ALC3246-CG_MQFN48_6X6-S]  29.59 23.01 270 top
UC1  SKL-U_BGA1356  [SKL-U_BGA_1356P-T]  123.48 28.54 270 bottom
UC2  -  [74AUP1G07GW_TSSOP5]  90.94 74.06 0 top
UC3  -  [W25Q128FVSIQ_SO8]  117.88 15.07 270 bottom
UC4  -  [SN74AHC1G08DCKR_SC70-5]  108.31 14.38 180 bottom
UC5  -  [SN74AHC1G08DCKR_SC70-5]  83.51 16.02 0 top
UC6  -  [74AUP1G07GW_TSSOP5]  88.14 14.17 270 top
UC7  -  [74AUP1G07GW_TSSOP5]  130.72 51.46 90 bottom
UC9  -  [SN74AHC1G08DCKR_SC70-5]  136.91 23.07 0 top
UE1  -  [MEC1404-NU-TR_VTQFP128_14X14]  140.33 18.78 0 bottom
UE2  -  [SN74LVC1G06DCKR_SC70-5]  153.6 22.84 180 top
UL1  RTL8106E-CG_QFN32_4X4  [RTL8106E-CG_QFN32_4X4-S]  36.15 114.73 180 bottom
UL3  -  [SY6288C20AAC_SOT23-5]  28.65 121 180 bottom
UU1  -  [SY6288D20AAC_SOT23-5]  17.93 49.16 270 top
UU3  -  [SY6288D20AAC_SOT23-5]  127.42 10.74 270 bottom
UV1  216-0842024-A11-MAR_FCBGA631  [216-0842024-A11-MAR_FCBGA_631P]  123.66 103.52 90 bottom
UV2  MC74VHC1G08DFT2G_SC70-5  [SN74AHC1G08DCKR_SC70-5]  98.52 103.52 180 bottom
UV12  H5GC4H24AJR-R0C_BGA170  [H5GC4H24AJR-R0C_BGA_170P]  137.83 117.25 90 top
UV13  H5GC4H24AJR-R0C_BGA170  [H5GC4H24AJR-R0C_BGA_170P]  150.63 117.25 90 bottom
UV14  H5GC4H24AJR-R0C_BGA170  [H5GC4H24AJR-R0C_BGA_170P]  150.63 110.63 270 top
UV15  H5GC4H24AJR-R0C_BGA170  [H5GC4H24AJR-R0C_BGA_170P]  137.83 110.63 270 bottom
UX1  TPS22967DSGR_SON8_2X2  [TPS22967DSGR_SON8_2X2-S]  219.11 50.58 90 top
UX2  PS8713BTQFN24GTR2-A0_TQFN24_4X4  [SN65LVPE502CPRGER_VQFN24_4X4-S]  213.99 39.07 180 bottom
UZ1  TPS22967DSGR_SON8_2X2  [TPS22967DSGR_SON8_2X2-S]  132.81 32.52 0 top
UZ2  -  [TPS22961DNYR_WSON8]  135.8 28.45 90 top
UZ3  EM5209VF_DFN14_3X2  [EM5209VF_DFN14_3X2-S]  168.26 24.16 180 top
UZ4  TPS22967DSGR_SON8_2X2  [TPS22967DSGR_SON8_2X2-S]  127.04 93.89 270 bottom
UZ5  EM5209VF_DFN14_3X2  [EM5209VF_DFN14_3X2-S]  116.26 93.22 270 bottom
YC1  24MHZ_12PF_X3G024000DC1H  [Y_X3G024000DC1H_4P]  131.49 47.29 90 bottom
YC2  32.768KHZ_9PF_X1A000141000200  [Y_X1A000141000200_2P]  92.26 25.74 180 top
YE1  32.768KHZ_9PF_X1A000141000200  [Y_X1A000141000200_2P]  144.41 11.97 180 bottom
YL1  25MHZ_10PF_7V25000014  [Y_7V25000014_4P]  38.16 122.29 0 bottom
YV1  27MHZ_10PF_7V27000050  [Y_7V27000011_4P]  96.69 125.9 270 bottom
ZT1  PAD  [TPC12]  156.74 111.52 0 top
ZT2  PAD  [TPC12]  156.61 102.89 0 top
ZT3  PAD  [TPC12]  154.26 106.32 0 top
ZT4  PAD  [TPC12]  30.5 4.21 0 top
ZT5  PAD  [TPC12]  30.5 2.43 0 top
ZT6  PAD  [TPC12]  30.31 8.53 0 top
ZT7  PAD  [TPC12]  30.44 6.56 0 top
ZT8  PAD  [TPC12]  106.51 10.11 0 top
ZT9  PAD  [TPC12]  107.79 4.23 0 top
ZT10  PAD  [TPC12]  100.99 9.99 0 top
ZT11  PAD  [TPC12]  99.4 9.48 0 top
ZT12  PAD  [TPC12]  110.13 4.21 0 top
ZT13  PAD  [TPC12]  112.22 4.21 0 top
ZT14  PAD  [TPC12]  148.99 31.26 0 top
ZT15  PAD  [TPC12]  184.61 51.2 0 top
ZT16  PAD  [TPC12]  149.02 12.49 0 top
ZT17  PAD  [TPC12]  156.04 12.15 0 top
ZT18  PAD  [TPC12]  15.56 16.29 0 top
ZT19  PAD  [TPC12]  15.01 11.12 0 top
ZT20  PAD  [TPC12]  11.7 24.72 0 top
ZT21  PAD  [TPC12]  8.72 25.1 0 top
ZT22  PAD  [TPC12]  14.88 13.05 0 top
ZT23  PAD  [TPC12]  19.31 15.07 0 top
ZT24  PAD  [TPC12]  89.58 22.97 0 top
ZT25  PAD  [TPC12]  64.79 9.35 0 top
ZT26  PAD  [TPC12]  65.36 7.26 0 top
ZT27  PAD  [TPC12]  66.38 9.86 0 top
ZT28  PAD  [TPC12]  67.14 7.07 0 top
ZT29  PAD  [TPC12]  68.07 10.89 0 top
ZT30  PAD  [TPC12]  68.92 6.5 0 top
ZT31  PAD  [TPC12]  69.74 9.86 0 top
ZT32  PAD  [TPC12]  70.63 6.43 0 top
ZT33  PAD  [TPC12]  71.2 10.88 0 top
ZT34  PAD  [TPC12]  71.97 7.45 0 top
ZT35  PAD  [TPC12]  72.85 9.73 0 top
ZT36  PAD  [TPC12]  73.24 5.99 0 top
ZT37  PAD  [TPC12]  74.12 11.19 0 top
ZT38  PAD  [TPC12]  74.7 7.45 0 top
ZT39  PAD  [TPC12]  75.46 9.8 0 top
ZT40  PAD  [TPC12]  76.28 11.38 0 top
ZT41  PAD  [TPC12]  76.16 6.11 0 top
ZT42  PAD  [TPC12]  77.81 7.64 0 top
ZT43  PAD  [TPC12]  78.32 11.7 0 top
ZT44  PAD  [TPC12]  79.14 9.86 0 top
ZT45  PAD  [TPC12]  80.22 11.32 0 top
ZT46  PAD  [TPC12]  81.94 8.08 0 top
ZT47  PAD  [TPC12]  81.55 9.99 0 top
ZT48  PAD  [TPC12]  83.29 9.49 0 top
ZT49  PAD  [TPC12]  84.79 10.37 0 top
ZT50  PAD  [TPC12]  86.44 9.1 0 top
ZT51  PAD  [TPC12]  119.82 9.66 0 top
ZT52  PAD  [TPC12]  111.34 9.16 0 top
ZT53  PAD  [TPC12]  129.62 12.91 0 top
ZT54  PAD  [TPC12]  130.96 11.89 0 top
ZT55  PAD  [TPC12]  131.21 10.05 0 top
ZT56  PAD  [TPC12]  132.23 13.48 0 top
ZT57  PAD  [TPC12]  134.97 10.62 0 top
ZT58  PAD  [TPC12]  135.4 9.35 0 top
ZT59  PAD  [TPC12]  90.62 4.34 0 top
ZT60  PAD  [TPC12]  128.23 8.78 0 top
ZT61  PAD  [TPC12]  116.35 9.86 0 top
ZT62  PAD  [TPC12]  21.31 97.87 0 top
ZT63  PAD  [TPC12]  57.51 98.24 180 bottom
ZT64  PAD  [TPC12]  10.53 10.13 0 top
ZT65  PAD  [TPC12]  29.78 96.37 0 top
ZT66  PAD  [TPC12]  28.75 95.48 0 top
ZT101  PAD  [TPC12]  168.27 118.27 0 top
ZT102  PAD  [TPC12]  169.65 122.46 0 top
ZT103  PAD  [TPC12]  164.12 122.69 0 top
ZT104  PAD  [TPC12]  213.44 14.2 0 top
ZT105  PAD  [TPC12]  216.25 16.9 0 top
ZT106  PAD  [TPC12]  218.02 17.48 0 top

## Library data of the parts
C1-C3 C5-C11 C13 C14 C16-C19 C21 C23-C27 C32-C34 CA2 CA4 CA6 CA7 CA9 CA10 CA14 CA16 CA17 CA27-CA31 CA34-CA37 CC1-CC16 CC26-CC35 CC39-CC58 CC60-CC73 CC75 CC78 CC79 CC82 CC85-CC90 CD3-CD5 CD9 CD11-CD18 CD28-CD31 CD35 CD36 CD39 CD41-CD48 CD58 CD59 CE1-CE4 CE6-CE23 CE25-CE33 CI1-CI9 CL1-CL6 CL8-CL12 CL14 CS1-CS6 CS9-CS14 CS16-CS19 CU1-CU7 CU17-CU19 CV1-CV8 CV11 CV15 CV17 CV18 CV20 CV21 CV26 CV28 CV29 CV33-CV35 CV39-CV42 CV46-CV53 CV56-CV60 CV62-CV66 CV71-CV80 CV82 CV85-CV87 CV89 CV90 CV92-CV121 CV123-CV127 CV153 CV155 CV157 CV158 CV160-CV162 CV164-CV166 CV169 CV170 CV173-CV181 CV198 CV210 CV211 CV213 CV216 CV219 CV221 CV227 CV230 CV233 CV235 CV242 CV243 CV247 CV248 CV304-CV309 CV312 CV313 CV333-CV336 CV341-CV344 CV390 CV391 CV394 CV395 CW1-CW4 CW7-CW9 CX1-CX13 CZ1-CZ23 CZ25-CZ31 EC2201-EC2216 EC2222 EC2223 EC2225 EC2226 EC2229 EC2230 EC2301 EC2302 EC2901 EC2902 EC3001 EC3002 EC3201 EC3202 PC1-PC4 PC7 PC8 PC14 PC16 PC100 PC102 PC103 PC113-PC116 PC127 PC128 PC130-PC133 PC200-PC203 PC207 PC208 PC210 PC213 PC214 PC230 PC231 PC301 PC302 PC304-PC307 PC309 PC320 PC321 PC502-PC504 PC601 PC602 PC605 PC611 PC613 PC614 PC616-PC621 PC624-PC633 PC636 PC637 PC639-PC647 PC649-PC655 PC659-PC661 PC666 PC667 PC671 PC677 PC679 PC680 PC685 PC686 PC688 PC691-PC695 PC705 PC708 PC711 PC721 PC742 PC744 PC747-PC749 PC751-PC753 PC765 PC768 PC769 PC777 PC779-PC781 PC790 PC801 PC803 PC805 PC1106-PC1108 PC1115-PC1120 PC1122-PC1124 PC1190-PC1193 PC1226-PC1229 PC1232 PC1233 PC1401 PC1402 PC1404-PC1407 PC1409 PC1420 PC1421 = C_0402
C4 C15 C20 C22 CA1 CA3 CA5 CA11-CA13 CA15 CA20-CA26 CA32 CA33 CC36-CC38 CC76 CC77 CC80 CC81 CC83 CC84 CD1 CD2 CD6-CD8 CD10 CD19-CD26 CD32-CD34 CD37 CD38 CD40 CD49-CD56 CE5 CE24 CL7 CV19 CV27 CV30 CV38 CV43-CV45 CV54 CV55 CV61 CV67-CV70 CV81 CV84 CV88 CV91 CV122 CV225 CV238 CW5 CW6 PC111 PC112 PC119 PC125 PC126 PC204 PC209 PC215-PC220 PC308 PC310-PC313 PC501 PC505-PC507 PC603 PC604 PC622 PC662 PC678 PC750 PC757 PC767 PC1001-PC1029 PC1057-PC1061 PC1064-PC1082 PC1109-PC1111 PC1121 PC1129-PC1146 PC1170-PC1184 PC1230 PC1231 PC1408 PC1411-PC1414 = C_0603
C30 CC59 CC74 CS7 CS15 CU8 CU9 CU20 CU21 PC104-PC110 PC117 PC118 PC120-PC124 PC205 PC206 PC211 PC212 PC303 PC608 PC612 PC656-PC658 PC672 PC673 PC760-PC764 PC766 PC775 PC776 PC778 PC802 PC804 PC1103-PC1105 PC1112-PC1114 PC1403 = C_0805
CD27 CD57 PC1062 PC1127 = C_D2
CL13 CU10 CU22 = C_1206
D1 = BAS40C_SOT23-3
D2 D5 D6 = RB551V-30_SOD323-2
D3 D4 DA3 = BAT54C-7-F_SOT23-3
D8 PD102 = SDMK0340L-7-F_SOD323-2
DA1 DA2 = AZ5125-02SPR7G_SOT23-3
DA4 = L03ESDL5V0CC3-2_SOT23-3
DA5 = AZ5123-02SPR7G_SOT23-3
DA6 = PESD5V0U2BT_SOT23-3
DE1 = AZ5125-01HPR7G_SOD523-2
DX1 = IP4292CZ10-TBR_XSON10_2P5X1
DX2 DX3 DZ1-DZ5 = RB751S40T1G_SOD523-2
ED2901 = AZ5725-01F_DFN2
EU2601 EU2603 EU3101 = L05ESDL5V0NA-4_SLP2510P8-10-9
EU2602 EU2604 = AZC199-02SPR7G_SOT23-3
EU3501 = TVWDF1004AD0_DFN9
F1 F2 = F_SMD1812P110TF-24
F3 = F_MF-NSMF050-2
FD1-FD4 = FIDUCIAL_C40M80
FI1 = F_1206L150PR
H1-H5 = H_3P0-G
H6 = H_5P6N
H7 = H_3P0N
H8-H10 = H_3P5
H11 = H_3P2
H12 = H_3P2X2P6
H13 = H_6P0
HCPU1 HCPU4 = H_3P7X4P3
HCPU2 = H_3P9
HCPU3 = H_3P7
J3D1 = ACES_50463-0104A-001_10P
JCMOS1 = SHORTPADS: User Part Number: PART#
JDB1 JDEG1 = JXT_FP241AH-010GAAM_10P
JDIMM1 = DEREN_40-42271-26001RHF_260P-T
JDIMM2 = DEREN_40-42261-26001RHF_260P-T
JEDP1 = ACES_51540-04001-P01_40P
JFAN1 JSPK1 = JXT_WB247H-004S10M_4P
JHDD1 = ACES_51625-01201-001_12P
JHDMI1 = CONCR_099AKAC19NBLCNF_19P
JHP1 = YUQIU_PJ753-F07J1BE-B_7P-T
JIOB1 = ACES_51524-0160N-001_16P
JKB1 = STARC_132C30-100020-A2-R_30P
JKBBL1 = ACES_51575-00401-001_4P-T
JLAN1 = SANTA_130460-N_8P-T
JLED1 = ACES_51524-0040N-001_4P
JODD1 = ACES_50673-0120N-001_12P-T
JP1 JP9 JP12 JP13 PJP105 PJP106 PJP203 PJP206 PJP301 PJP501 PJP502 PJP801 PJP802 PJP1101 PJP1401 = JUMP_43X79
JP2 JP8 JP10 JP11 PJP603 = JUMP_43X39
JP4-JP7 PJP102 PJP103 PJP200 PJP302 PJP601 PJP701 PJP1402 = JUMP_43X118
JPWR1 = JXT_FP226H-006S1BM_6P
JRTC1 = ACES_50271-0020N-001_2P
JSSD1 = ACES_50406-03071-001_30P
JTP1 = JXT_FP202DH-008M10M_8P
JUSB1 JUSB2 = ACON_TARA4-9K1311_9P
JWLAN1 = LCN_DAN05-67406-0100_67P
L1 L2 = MURAT_BLM15BD601SN1D_2P
L3 LU1 LU4 LU7 LU8 = INPAQ_MCM1012B900F06BP_4P
L4 LW1 = INPAQ_MCM1012B900F06BP_4P-NPM
L5 = MURAT_BLM15PX221SN1D_2P
LI1-LI4 LU2 LU3 LU5 LU6 = INPAQ_HCM1012GH900BP_4P-NPM
LV2-LV4 LV7 LV8 PH601-PH605 PH1101 PH1102 PR2-PR4 PR6-PR13 PR15 PR16 PR18 PR20 PR28 PR29 PR31-PR33 PR102 PR103 PR107-PR110 PR113-PR115 PR117 PR118 PR122 PR204 PR205 PR207-PR209 PR302 PR305 PR308-PR310 PR502-PR505 PR601 PR604 PR605 PR608 PR610-PR613 PR617 PR618 PR621-PR623 PR626 PR628-PR633 PR635-PR654 PR656 PR657 PR662 PR673 PR678 PR680 PR727 PR729 PR731 PR732 PR737 PR738 PR740-PR742 PR745 PR749-PR757 PR760 PR762-PR764 PR774 PR777 PR781 PR790 PR791 PR801 PR802 PR1101 PR1104-PR1106 PR1110-PR1113 PR1115 PR1117 PR1119-PR1121 PR1124 PR1128-PR1137 PR1140 PR1401 PR1404 PR1406 PR1407 PR1409-PR1411 R1 R2 R5 R6 R9 R10 R19-R35 R38-R43 R45-R50 R53 R56 R57 RA3 RA7-RA12 RA23-RA34 RA41 RA42 RC1-RC16 RC18-RC78 RC80 RC82 RC84-RC96 RC100 RC102-RC105 RC108-RC134 RC136-RC148 RC150-RC160 RC164 RC175-RC182 RC187-RC192 RD1-RD3 RD7 RD9-RD13 RD15 RD17 RD19-RD24 RE1 RE3 RE4 RE6 RE8-RE21 RE23-RE27 RE29 RE30 RE32-RE35 RE40 RE41 RE43-RE49 RE51-RE59 RI1-RI16 RL1-RL4 RL6 RL7 RL16 RS1 RU3-RU6 RU9-RU12 RV1-RV6 RV8 RV9 RV11-RV13 RV15-RV17 RV20 RV21 RV28 RV29 RV32-RV41 RV48-RV55 RV59 RV79-RV89 RV116-RV121 RV123 RV131-RV135 RV151-RV154 RV162 RV163 RV260 RV368 RV369 RW1 RW2 RW6 RW8 RX1-RX3 RX5 RX6 RX10-RX31 RZ1-RZ3 RZ6-RZ9 = R_0402
LV6 = MURAT_BLM15BB221SN1D_2P
LX1 LX2 = TAIYO_MCF12102G900-T_4P
PBATT1 = ACES_50458-01001-P01_10P-T
PC606 PC690 = C_25CL33LD
PC836-PC839 PC1063 PC1128 = C_5X4P5
PC1030-PC1056 PC1083-PC1099 PC1125 PC1126 PC1147-PC1153 PC1164 = C_0201
PD2-PD4 = TVNST52302AB0_SOT523-3
PD5 PD6 = BAV99W_SC70-3
PD704 = LRB715FT1G_SOT323-3
PJP1-PJP3 = JUMP_43X79-NPM
PJPDC1 = ACES_50458-00601-001_6P-T
PL1 PL3 PL4 = 5A_Z150_1210_2P
PL2 = MURAT_BLM15AG102SN1D_2P
PL100 PL101 PL200 PL700 = L_7X7X3_M_2P
PL102 PL103 PL201 PL302 PL602 PL1101 PL1402 = 5A_Z150_1210_2P-NPM
PL301 PL501 PL1401 = L_5X5X3_M_2P
PL601 = L_5X5X3_M
PL603 PL605 PL1102 PL1103 = L_7X7X4_M
PL704 = L_5X5X3_M_2P-NPM
PQ1 PQ2 = 2N7002DW-T-R7_SOT363-6
PQ3 PQ709 PQ712 = L2N7002WT1G_SC70-3
PQ5 = RHU002N06_SOT323-3
PQ6 = FDV301N_NL_SOT23-3
PQ201 PQ601 = AON7934_DFN3X3A8-10
PQ704 PQ708 = SIS412DN-T1-GE3_POWERPAK8-5
PQ710 = LMUN5113T1G_SOT323-3
PQ711 = LTC015EUBFS8TL_UMT3F
PQ717 PQ718 PQ740 = MDU1512RH_POWERDFN56-8-5
PQ720 PQ721 = RUM002N02GT2L_VMT3
PQ1101-PQ1106 = SIR472DP-T1-GE3_POWERPAK8-5
PR5 PR106 PR112 PR203 PR307 PR506 PR627 PR663 PR676 PR743 PR766 PR1107 PR1125 PR1408 = R_1206
PR100 PR111 PR200 PR306 PR761 PR771 PR773 PR1103 PR1123 PR1402 R55 RA4 RA39 RC17 RC161-RC163 RC169-RC171 RC173 RC174 RE2 RE7 RE50 RL5 RV27 RV30 RV31 RV364 = R0603_0OHM
PR116 PR120 PR121 PR201 PR202 PR301 PR303 PR304 PR501 PR602 PR603 PR606 PR607 PR609 PR616 PR620 PR625 PR655 PR659 PR671 PR679 PR769 PR770 PR772 PR775 PR776 PR778 PR779 PR803 PR1116 PR1122 PR1138 PR1139 PR1403 PR1405 R8 RA2 RA5 RA6 RA17 RA18 RA36 RA37 RA40 RC83 RC97 RC99 RC106 RC107 RD4-RD6 RD8 RD14 RD16 RD18 RE22 RE28 RE37 RE38 RE42 RE60 RE61 RE63 RE64 RL12 RL13 RV155-RV159 RW4 RW9 = R0402_0OHM
PR206 PR210 PR619 PR624 PR660 PR661 PR672 PR674 PR780 PR1108 PR1114 PR1126 R11-R13 R16 R36 R37 R44 RC149 RL14 RL15 RZ4 = R_0603
PR703 PR765 = R_1206_4P
PU100 = SY8286BRAC_QFN20_3X3-S
PU102 = SY8286CRAC_QFN20_3X3-S
PU200 = RT8207PGQW_WQFN20_3X3-S
PU300 PU1400 = SY8286RAC_QFN20_3X3-S
PU500 = SY8033BDBC_DFN10_3X3-S
PU602 = ISL62883CHRTZ-T_TQFN40_5X5-S
PU603 PU605 = AOZ5019QI_QFN23_5X3P5
PU606 = ISL95808HRZ-TS2378_DFN8_2X2-S
PU703 = ISL95520HRZ-T_QFN32_4X4-S
PU800 = RT904225GSP_SO8
PU1100 = ISL62771HRTZ-T_TQFN40_5X5-S
Q1 Q5 Q12 Q13 QC2 QI1 = 2N7002K_SOT23-3
Q2 Q10 Q11 QC1 QI2 = DMN66D0LDW-7_SOT363-6
Q3 Q4 Q7 Q15 = DDTA144VCA-7-F_SOT23-3
Q6 Q8 Q9 Q16 QA1 = LN2306LT1G_SOT23-3
Q14 = LMBT3904LT1G_SOT23-3
QI3 = SSM3K7002FU_SC70-3
QV1 = 2N7002KDWH_SOT363-6
R3 R54 RW3 RW5 = R_0805
R17 R18 RU1 RU2 RU7 RU8 RU13-RU16 RX4 RX7-RX9 = R_0402-NPM
R51 RA1 RA22 = R0805_0OHM
RA13-RA16 = MURAT_BLM15PD600SN1D_2P
RA35 RA38 = MURAT_BLM15PX330SN1D_2P
RP1 RP2 RP34 RPC1 RPE1-RPE6 RPI1 RPI2 = RP_0804_8P4R
SW1 = SW_TST71-N-220-T170-S017_2P
TL1 = MHPC_NS681677_12P
TP1-TP44 TP46-TP75 TPC1-TPC33 TPS1-TPS7 TPS9 TPS10 ZT1-ZT66 ZT101-ZT106 = TPC12
U1 UL3 = SY6288C20AAC_SOT23-5
U2 = NCT7718W_MSOP8
UA1 = ALC3246-CG_MQFN48_6X6-S
UC1 = SKL-U_BGA_1356P-T
UC2 UC6 UC7 = 74AUP1G07GW_TSSOP5
UC3 = W25Q128FVSIQ_SO8
UC4 UC5 UC9 UV2 = SN74AHC1G08DCKR_SC70-5
UE1 = MEC1404-NU-TR_VTQFP128_14X14
UE2 = SN74LVC1G06DCKR_SC70-5
UL1 = RTL8106E-CG_QFN32_4X4-S
UU1 UU3 = SY6288D20AAC_SOT23-5
UV1 = 216-0842024-A11-MAR_FCBGA_631P
UV12-UV15 = H5GC4H24AJR-R0C_BGA_170P
UX1 UZ1 UZ4 = TPS22967DSGR_SON8_2X2-S
UX2 = SN65LVPE502CPRGER_VQFN24_4X4-S
UZ2 = TPS22961DNYR_WSON8
UZ3 UZ5 = EM5209VF_DFN14_3X2-S
YC1 = Y_X3G024000DC1H_4P
YC2 YE1 = Y_X1A000141000200_2P
YL1 = Y_7V25000014_4P
YV1 = Y_7V27000011_4P

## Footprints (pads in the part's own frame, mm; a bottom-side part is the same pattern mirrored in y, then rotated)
2N7002DW-T-R7_SOT363-6
  oval 0.381x1.397 smd: 1(0,0) 2(0.65,0) 3(1.3,0) 4(1.3,1.725) 5(0.65,1.725) 6(0,1.725)
2N7002K_SOT23-3
  oval 1.016x1.524 smd: 1(0,0) 2(0.965,2.083) 3(-0.965,2.083)
2N7002KDWH_SOT363-6
  oval 0.356x0.889 smd: 1(0,0) 2(0.65,0) 3(1.3,0) 4(1.3,1.6) 5(0.65,1.6) 6(0,1.6)
5A_Z150_1210_2P
  rect 0.991x2.997 smd: 1(0,0) 2(2.7,0)
5A_Z150_1210_2P-NPM
  rect 0.991x2.997 smd: 1(0,0) 2(2.7,0)
74AUP1G07GW_TSSOP5
  oval 0.381x1.346 smd: 1(0,0) 2(0.65,0) 3(1.3,0) 4(1.3,1.79) 5(0,1.79)
216-0842024-A11-MAR_FCBGA_631P
  round 0.406 smd: A3(0.8,0) A30(20.8,0) A32(21.6,0) AB7(3.2,-15) AB8(4,-15) AB9(4.8,-15) AB10(5.6,-15) AB23(16,-15) AB24(16.8,-15) AB25(17.6,-15) AB26(18.4,-15) AC11(6.6,-16) AC13(7.8,-16) AC14(9,-16) AC16(10.2,-16) AC17(11.4,-16) AC19(12.6,-16) AC20(13.8,-16) AC22(15,-16) AD11(6.6,-16.8) AD13(7.8,-16.8) AD14(9,-16.8) AD16(10.2,-16.8) AD17(11.4,-16.8) AD19(12.6,-16.8) AD20(13.8,-16.8) AD22(15,-16.8) AE11(6.6,-17.6) AE13(7.8,-17.6) AE14(9,-17.6) AE16(10.2,-17.6) AE17(11.4,-17.6) AE19(12.6,-17.6) AE20(13.8,-17.6) AE22(15,-17.6) AF11(6.6,-18.4) AF13(7.8,-18.4) AF14(9,-18.4) AF16(10.2,-18.4) AF17(11.4,-18.4) AF19(12.6,-18.4) AF20(13.8,-18.4) AF22(15,-18.4) AK1(0,-20.8) AK3(0.8,-20.8) AK30(20.8,-20.8) AK32(21.6,-20.8) AM1(0,-21.6) AM3(0.8,-21.6) AM30(20.8,-21.6) AM32(21.6,-21.6) C1(0,-0.8) C3(0.8,-0.8) C30(20.8,-0.8) C32(21.6,-0.8) G11(6.6,-3.2) G13(7.8,-3.2) G14(9,-3.2) G16(10.2,-3.2) G17(11.4,-3.2) G19(12.6,-3.2) G20(13.8,-3.2) G22(15,-3.2) H11(6.6,-4) H13(7.8,-4) H14(9,-4) H16(10.2,-4) H17(11.4,-4) H19(12.6,-4) H20(13.8,-4) H22(15,-4) J11(6.6,-4.8) J13(7.8,-4.8) J14(9,-4.8) J16(10.2,-4.8) J17(11.4,-4.8) J19(12.6,-4.8) J20(13.8,-4.8) J22(15,-4.8) K11(6.6,-5.6) K13(7.8,-5.6) K14(9,-5.6) K16(10.2,-5.6) K17(11.4,-5.6) K19(12.6,-5.6) K20(13.8,-5.6) K22(15,-5.6) L7(3.2,-6.6) L8(4,-6.6) L9(4.8,-6.6) L10(5.6,-6.6) L23(16,-6.6) L24(16.8,-6.6) L25(17.6,-6.6) L26(18.4,-6.6) N7(3.2,-7.8) N8(4,-7.8) N9(4.8,-7.8) N10(5.6,-7.8) N23(16,-7.8) N24(16.8,-7.8) N25(17.6,-7.8) N26(18.4,-7.8) P7(3.2,-9) P8(4,-9) P9(4.8,-9) P10(5.6,-9) P23(16,-9) P24(16.8,-9) P25(17.6,-9) P26(18.4,-9) T7(3.2,-10.2) T8(4,-10.2) T9(4.8,-10.2) T10(5.6,-10.2) T23(16,-10.2) T24(16.8,-10.2) T25(17.6,-10.2) T26(18.4,-10.2) U7(3.2,-11.4) U8(4,-11.4) U9(4.8,-11.4) U10(5.6,-11.4) U23(16,-11.4) U24(16.8,-11.4) U25(17.6,-11.4) U26(18.4,-11.4) W7(3.2,-12.6) W8(4,-12.6) W9(4.8,-12.6) W10(5.6,-12.6) W23(16,-12.6) W24(16.8,-12.6) W25(17.6,-12.6) W26(18.4,-12.6) Y7(3.2,-13.8) Y8(4,-13.8) Y9(4.8,-13.8) Y10(5.6,-13.8) Y23(16,-13.8) Y24(16.8,-13.8) Y25(17.6,-13.8) Y26(18.4,-13.8)
  round 0.305 smd: A5(1.6,0) A7(3.2,0) A9(4.8,0) A11(6.4,0) A13(8,0) A15(9.6,0) A17(11.2,0) A19(12.8,0) A21(14.4,0) A23(16,0) A25(17.6,0) A27(19.2,0) A28(20,0) AA1(0,-14.4) AA3(0.8,-14.4) AA5(1.6,-14.4) AA6(2.4,-14.4) AA27(19.2,-14.4) AA29(20.4,-14.4) AA31(21.2,-14.4) AB2(0.4,-15.2) AB4(1.2,-15.2) AB6(2.4,-15.2) AB27(19.2,-15.2) AB28(20,-15.2) AB30(20.8,-15.2) AB32(21.6,-15.2) AC1(0,-16) AC3(0.8,-16) AC5(1.6,-16) AC6(2.4,-16) AC7(3.2,-16) AC8(4,-16) AC9(4.8,-16) AC10(5.6,-16) AC23(16,-16) AC24(16.8,-16) AC25(17.6,-16) AC26(18.4,-16) AC27(19.2,-16) AC29(20.4,-16) AC31(21.2,-16) AD2(0.4,-16.8) AD4(1.2,-16.8) AD6(2.4,-16.8) AD7(3.2,-16.8) AD8(4,-16.8) AD9(4.8,-16.8) AD10(5.6,-16.8) AD23(16,-16.8) AD24(16.8,-16.8) AD25(17.6,-16.8) AD26(18.4,-16.8) AD27(19.2,-16.8) AD28(20,-16.8) AD30(20.8,-16.8) AD32(21.6,-16.8) AE1(0,-17.6) AE3(0.8,-17.6) AE5(1.6,-17.6) AE6(2.4,-17.6) AE7(3.2,-17.6) AE8(4,-17.6) AE9(4.8,-17.6) AE10(5.6,-17.6) AE23(16,-17.6) AE24(16.8,-17.6) AE25(17.6,-17.6) AE26(18.4,-17.6) AE27(19.2,-17.6) AE29(20.4,-17.6) AE31(21.2,-17.6) AF2(0.4,-18.4) AF4(1.2,-18.4) AF6(2.4,-18.4) AF7(3.2,-18.4) AF8(4,-18.4) AF9(4.8,-18.4) AF10(5.6,-18.4) AF23(16,-18.4) AF24(16.8,-18.4) AF25(17.6,-18.4) AF26(18.4,-18.4) AF27(19.2,-18.4) AF28(20,-18.4) AF30(20.8,-18.4) AF32(21.6,-18.4) AG1(0,-19.2) AG3(0.8,-19.2) AG5(1.6,-19.2) AG6(2.4,-19.2) AG7(3.2,-19.2) AG8(4,-19.2) AG9(4.8,-19.2) AG10(5.6,-19.2) AG11(6.4,-19.2) AG12(7.2,-19.2) AG13(8,-19.2) AG14(8.8,-19.2) AG15(9.6,-19.2) AG16(10.4,-19.2) AG17(11.2,-19.2) AG18(12,-19.2) AG19(12.8,-19.2) AG20(13.6,-19.2) AG21(14.4,-19.2) AG22(15.2,-19.2) AG23(16,-19.2) AG24(16.8,-19.2) AG25(17.6,-19.2) AG26(18.4,-19.2) AG27(19.2,-19.2) AG29(20.4,-19.2) AG31(21.2,-19.2) AH1(0,-20) AH3(0.8,-20) AH5(1.6,-20) AH6(2.4,-20) AH8(4,-20) AH10(5.6,-20) AH12(7.2,-20) AH14(8.8,-20) AH16(10.4,-20) AH18(12,-20) AH20(13.6,-20) AH22(15.2,-20) AH24(16.8,-20) AH26(18.4,-20) AH28(20,-20) AH30(20.8,-20) AH32(21.6,-20) AJ7(3.2,-20.4) AJ9(4.8,-20.4) AJ11(6.4,-20.4) AJ13(8,-20.4) AJ15(9.6,-20.4) AJ17(11.2,-20.4) AJ19(12.8,-20.4) AJ21(14.4,-20.4) AJ23(16,-20.4) AJ25(17.6,-20.4) AJ27(19.2,-20.4) AK5(1.6,-20.8) AK6(2.4,-20.8) AK8(4,-20.8) AK10(5.6,-20.8) AK12(7.2,-20.8) AK14(8.8,-20.8) AK16(10.4,-20.8) AK18(12,-20.8) AK20(13.6,-20.8) AK22(15.2,-20.8) AK24(16.8,-20.8) AK26(18.4,-20.8) AK28(20,-20.8) AL7(3.2,-21.2) AL9(4.8,-21.2) AL11(6.4,-21.2) AL13(8,-21.2) AL15(9.6,-21.2) AL17(11.2,-21.2) AL19(12.8,-21.2) AL21(14.4,-21.2) AL23(16,-21.2) AL25(17.6,-21.2) AL27(19.2,-21.2) AM5(1.6,-21.6) AM6(2.4,-21.6) AM8(4,-21.6) AM10(5.6,-21.6) AM12(7.2,-21.6) AM14(8.8,-21.6) AM16(10.4,-21.6) AM18(12,-21.6) AM20(13.6,-21.6) AM22(15.2,-21.6) AM24(16.8,-21.6) AM26(18.4,-21.6) AM28(20,-21.6) B6(2.4,-0.4) B8(4,-0.4) B10(5.6,-0.4) B12(7.2,-0.4) B14(8.8,-0.4) B16(10.4,-0.4) B18(12,-0.4) B20(13.6,-0.4) B22(15.2,-0.4) B24(16.8,-0.4) B26(18.4,-0.4) C5(1.6,-0.8) C7(3.2,-0.8) C9(4.8,-0.8) C11(6.4,-0.8) C13(8,-0.8) C15(9.6,-0.8) C17(11.2,-0.8) C19(12.8,-0.8) C21(14.4,-0.8) C23(16,-0.8) C25(17.6,-0.8) C27(19.2,-0.8) C28(20,-0.8) D6(2.4,-1.2) D8(4,-1.2) D10(5.6,-1.2) D12(7.2,-1.2) D14(8.8,-1.2) D16(10.4,-1.2) D18(12,-1.2) D20(13.6,-1.2) D22(15.2,-1.2) D24(16.8,-1.2) D26(18.4,-1.2) E1(0,-1.6) E3(0.8,-1.6) E5(1.6,-1.6) E7(3.2,-1.6) E9(4.8,-1.6) E11(6.4,-1.6) E13(8,-1.6) E15(9.6,-1.6) E17(11.2,-1.6) E19(12.8,-1.6) E21(14.4,-1.6) E23(16,-1.6) E25(17.6,-1.6) E27(19.2,-1.6) E28(20,-1.6) E30(20.8,-1.6) E32(21.6,-1.6) F2(0.4,-2.4) F4(1.2,-2.4) F6(2.4,-2.4) F7(3.2,-2.4) F8(4,-2.4) F9(4.8,-2.4) F10(5.6,-2.4) F11(6.4,-2.4) F12(7.2,-2.4) F13(8,-2.4) F14(8.8,-2.4) F15(9.6,-2.4) F16(10.4,-2.4) F17(11.2,-2.4) F18(12,-2.4) F19(12.8,-2.4) F20(13.6,-2.4) F21(14.4,-2.4) F22(15.2,-2.4) F23(16,-2.4) F24(16.8,-2.4) F25(17.6,-2.4) F26(18.4,-2.4) F27(19.2,-2.4) F28(20,-2.4) F30(20.8,-2.4) F32(21.6,-2.4) G1(0,-3.2) G3(0.8,-3.2) G5(1.6,-3.2) G6(2.4,-3.2) G7(3.2,-3.2) G8(4,-3.2) G9(4.8,-3.2) G10(5.6,-3.2) G23(16,-3.2) G24(16.8,-3.2) G25(17.6,-3.2) G26(18.4,-3.2) G27(19.2,-3.2) G29(20.4,-3.2) G31(21.2,-3.2) H2(0.4,-4) H4(1.2,-4) H6(2.4,-4) H7(3.2,-4) H8(4,-4) H9(4.8,-4) H10(5.6,-4) H23(16,-4) H24(16.8,-4) H25(17.6,-4) H26(18.4,-4) H27(19.2,-4) H28(20,-4) H30(20.8,-4) H32(21.6,-4) J1(0,-4.8) J3(0.8,-4.8) J5(1.6,-4.8) J6(2.4,-4.8) J7(3.2,-4.8) J8(4,-4.8) J9(4.8,-4.8) J10(5.6,-4.8) J23(16,-4.8) J24(16.8,-4.8) J25(17.6,-4.8) J26(18.4,-4.8) J27(19.2,-4.8) J29(20.4,-4.8) J31(21.2,-4.8) K2(0.4,-5.6) K4(1.2,-5.6) K6(2.4,-5.6) K7(3.2,-5.6) K8(4,-5.6) K9(4.8,-5.6) K10(5.6,-5.6) K23(16,-5.6) K24(16.8,-5.6) K25(17.6,-5.6) K26(18.4,-5.6) K27(19.2,-5.6) K28(20,-5.6) K30(20.8,-5.6) K32(21.6,-5.6) L1(0,-6.4) L3(0.8,-6.4) L5(1.6,-6.4) L6(2.4,-6.4) L27(19.2,-6.4) L29(20.4,-6.4) L31(21.2,-6.4) M2(0.4,-7.2) M4(1.2,-7.2) M6(2.4,-7.2) M27(19.2,-7.2) M28(20,-7.2) M30(20.8,-7.2) M32(21.6,-7.2) N1(0,-8) N3(0.8,-8) N5(1.6,-8) N6(2.4,-8) N27(19.2,-8) N29(20.4,-8) N31(21.2,-8) P2(0.4,-8.8) P4(1.2,-8.8) P6(2.4,-8.8) P27(19.2,-8.8) P28(20,-8.8) P30(20.8,-8.8) P32(21.6,-8.8) R1(0,-9.6) R3(0.8,-9.6) R5(1.6,-9.6) R6(2.4,-9.6) R27(19.2,-9.6) R29(20.4,-9.6) R31(21.2,-9.6) T2(0.4,-10.4) T4(1.2,-10.4) T6(2.4,-10.4) T27(19.2,-10.4) T28(20,-10.4) T30(20.8,-10.4) T32(21.6,-10.4) U1(0,-11.2) U3(0.8,-11.2) U5(1.6,-11.2) U6(2.4,-11.2) U27(19.2,-11.2) U29(20.4,-11.2) U31(21.2,-11.2) V2(0.4,-12) V4(1.2,-12) V6(2.4,-12) V27(19.2,-12) V28(20,-12) V30(20.8,-12) V32(21.6,-12) W1(0,-12.8) W3(0.8,-12.8) W5(1.6,-12.8) W6(2.4,-12.8) W27(19.2,-12.8) W29(20.4,-12.8) W31(21.2,-12.8) Y2(0.4,-13.6) Y4(1.2,-13.6) Y6(2.4,-13.6) Y27(19.2,-13.6) Y28(20,-13.6) Y30(20.8,-13.6) Y32(21.6,-13.6)
  round 0.508 smd: AA11(6.4,-14.2) AA12(7.4,-14.2) AA13(8.4,-14.2) AA15(9.4,-14.2) AA16(10.4,-14.2) AA17(11.2,-14.2) AA18(12.2,-14.2) AA20(13.2,-14.2) AA21(14.2,-14.2) AA22(15.2,-14.2) AB11(6.4,-15.2) AB12(7.4,-15.2) AB13(8.4,-15.2) AB15(9.4,-15.2) AB16(10.4,-15.2) AB17(11.2,-15.2) AB18(12.2,-15.2) AB20(13.2,-15.2) AB21(14.2,-15.2) AB22(15.2,-15.2) L11(6.4,-6.4) L12(7.4,-6.4) L13(8.4,-6.4) L15(9.4,-6.4) L16(10.4,-6.4) L17(11.2,-6.4) L18(12.2,-6.4) L20(13.2,-6.4) L21(14.2,-6.4) L22(15.2,-6.4) M11(6.4,-7.4) M12(7.4,-7.4) M13(8.4,-7.4) M15(9.4,-7.4) M16(10.4,-7.4) M17(11.2,-7.4) M18(12.2,-7.4) M20(13.2,-7.4) M21(14.2,-7.4) M22(15.2,-7.4) N11(6.4,-8.4) N12(7.4,-8.4) N13(8.4,-8.4) N15(9.4,-8.4) N16(10.4,-8.4) N17(11.2,-8.4) N18(12.2,-8.4) N20(13.2,-8.4) N21(14.2,-8.4) N22(15.2,-8.4) R11(6.4,-9.4) R12(7.4,-9.4) R13(8.4,-9.4) R15(9.4,-9.4) R16(10.4,-9.4) R17(11.2,-9.4) R18(12.2,-9.4) R20(13.2,-9.4) R21(14.2,-9.4) R22(15.2,-9.4) T11(6.4,-10.4) T12(7.4,-10.4) T13(8.4,-10.4) T15(9.4,-10.4) T16(10.4,-10.4) T17(11.2,-10.4) T18(12.2,-10.4) T20(13.2,-10.4) T21(14.2,-10.4) T22(15.2,-10.4) U11(6.4,-11.2) U12(7.4,-11.2) U13(8.4,-11.2) U15(9.4,-11.2) U16(10.4,-11.2) U17(11.2,-11.2) U18(12.2,-11.2) U20(13.2,-11.2) U21(14.2,-11.2) U22(15.2,-11.2) V11(6.4,-12.2) V12(7.4,-12.2) V13(8.4,-12.2) V15(9.4,-12.2) V16(10.4,-12.2) V17(11.2,-12.2) V18(12.2,-12.2) V20(13.2,-12.2) V21(14.2,-12.2) V22(15.2,-12.2) Y11(6.4,-13.2) Y12(7.4,-13.2) Y13(8.4,-13.2) Y15(9.4,-13.2) Y16(10.4,-13.2) Y17(11.2,-13.2) Y18(12.2,-13.2) Y20(13.2,-13.2) Y21(14.2,-13.2) Y22(15.2,-13.2)
